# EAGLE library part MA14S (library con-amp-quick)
AMP QUICK CONNECTOR
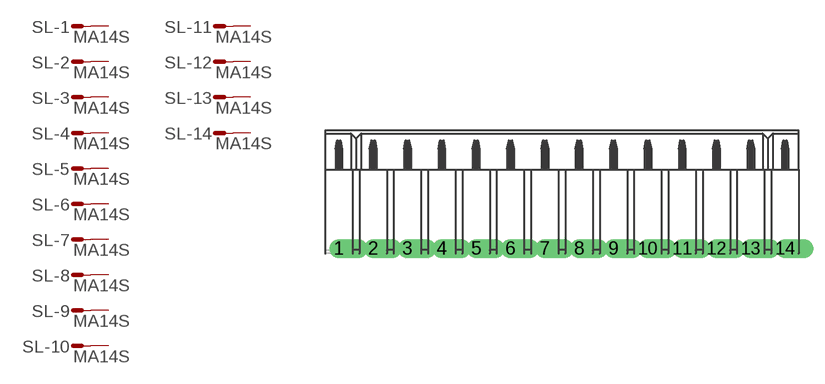
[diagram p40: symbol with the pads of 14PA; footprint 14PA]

Designator prefix SL; gates -1=M -2=M -3=M -4=M -5=M -6=M -7=M -8=M -9=M -10=M -11=M -12=M -13=M -14=M

## MA14S  [14PA]
1  -1:S  pas
2  -2:S  pas
3  -3:S  pas
4  -4:S  pas
5  -5:S  pas
6  -6:S  pas
7  -7:S  pas
8  -8:S  pas
9  -9:S  pas
10  -10:S  pas
11  -11:S  pas
12  -12:S  pas
13  -13:S  pas
14  -14:S  pas

## Footprint 14PA (pad centres in mm)
AMP QUICK CONNECTOR
drill 0.914 offset: 1 -16.51,0; 2 -13.97,0; 3 -11.43,0; 4 -8.89,0; 5 -6.35,0; 6 -3.81,0; 7 -1.27,0; 8 1.27,0; 9 3.81,0; 10 6.35,0; 11 8.89,0; 12 11.43,0; 13 13.97,0; 14 16.51,0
